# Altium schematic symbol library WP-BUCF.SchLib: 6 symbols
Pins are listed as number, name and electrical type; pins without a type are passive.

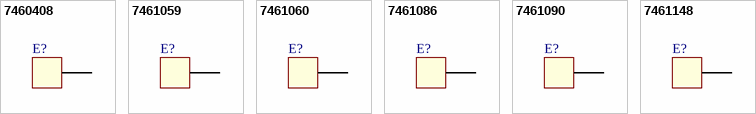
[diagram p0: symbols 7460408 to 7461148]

## 7460408
designator E?
REDCUBE PRESS-FIT with internal thread, circumference WP-BUCF, M5, 6 mm; Part Number: 7460408; Pin Number: 12; Rated Current: 175 A; Thread Length: 6 mm
footprint 7460408_Chemical Surface (M5, thr 6mm)
footprint 7460408_HAL Surface (M5, thr 6mm)
pins: 1

## 7461059
designator E?
REDCUBE PRESS-FIT with internal thread, circumference WP-BUCF, M6, 13.5 mm; Part Number: 7461059; Pin Number: 16; Rated Current: 240 A; Thread Length: 13.5 mm
footprint 7461059_Chemical Surface (M6, thr 13.5mm)
footprint 7461059_HAL Surface (M6, thr 13.5mm)
pins: 1

## 7461060
designator E?
REDCUBE PRESS-FIT with internal thread, circumference WP-BUCF, M10, 17.5 mm; Part Number: 7461060; Pin Number: 20; Rated Current: 340 A; Thread Length: 17.5 mm
footprint 7461060_Chemical Surface (M10, thr 17.5mm)
footprint 7461060_HAL Surface (M10, thr 17.5mm)
pins: 1

## 7461086
designator E?
REDCUBE PRESS-FIT with internal thread, circumference WP-BUCF, M4, 6 mm; Part Number: 7461086; Pin Number: 12; Rated Current: 175 A; Thread Length: 6 mm
footprint 7461086_Chemical Surface (M4, thr 6mm)
footprint 7461086_HAL Surface (M4, thr 6mm)
pins: 1

## 7461090
designator E?
REDCUBE PRESS-FIT with internal thread, circumference WP-BUCF, M8, 13.5 mm; Part Number: 7461090; Pin Number: 20; Rated Current: 340 A; Thread Length: 13.5 mm
footprint 7461090_Chemical Surface (M8, thr 13.5mm)
footprint 7461090_HAL Surface (M8, thr 13.5mm)
pins: 1

## 7461148
designator E?
REDCUBE PRESS-FIT with internal thread, circumference WP-BUCF, M2.5, 6 mm; Part Number: 7461148; Pin Number: 8; Rated Current: 130 A; Thread Length: 6 mm
footprint 7461148_Chemical Surface (M2.5, thr 6mm)
footprint 7461148_HAL Surface (M2.5, thr 6mm)
pins: 1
